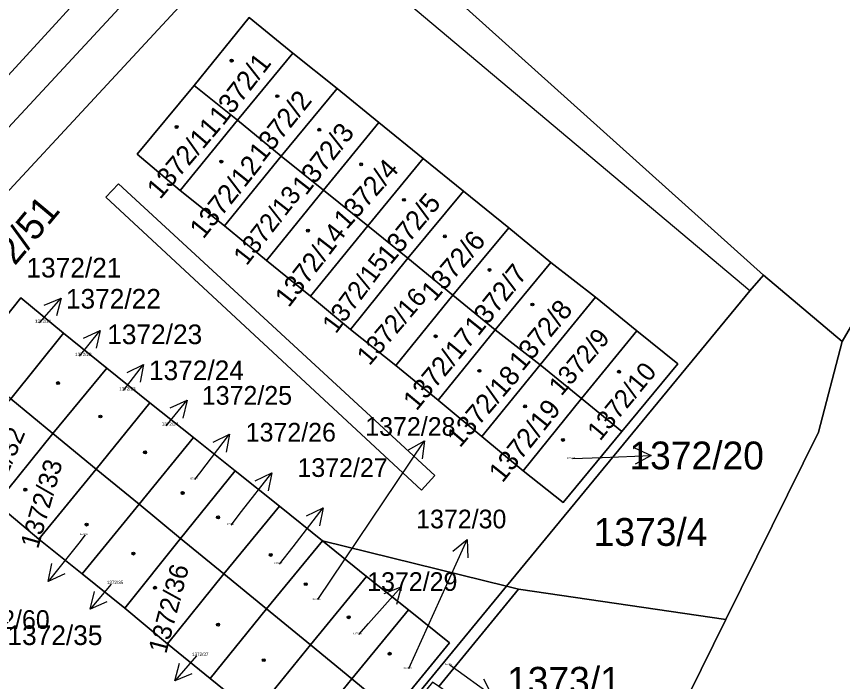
# Model space of a CAD drawing. Extents: x -598934 to -598196, y -1162208 to -1161502.
# Drawn here: x -598490.4 to -598440, y -1161798.5 to -1161757.9 of the extents above; entities that cross this region are included whole.
import ezdxf

# ---------------------------------------------------------------- set-up
doc = ezdxf.new("R2010")
doc.units = 0
for name, color, linetype in [('KN_CAR_KR', 7, 'Continuous'), ('KN_KULTURY', 7, 'Continuous'), ('KN_PARC_CIS_POM', 7, 'Continuous'), ('KN_PARC_CIS_POZ', 7, 'Continuous'), ('KN_PARC_CIS_STAV', 7, 'Continuous'), ('KN_PARC_PLOCHA', 7, 'Continuous'), ('PARC_C_SIPKA', 7, 'Continuous'), ('parcely_l', 7, 'Continuous')]:
    doc.layers.add(name, color=color, linetype=linetype)

msp = doc.modelspace()

# ---------------------------------------------------------------- linework, layer by layer
at = {"layer": 'KN_CAR_KR'}
for points in [[(-598477.15, -1161746.44), (-598498.32, -1161769.54)], [(-598474.27, -1161750.6), (-598503.05, -1161781.64)], [(-598445.66, -1161774.67), (-598474.27, -1161750.6)], [(-598484.99, -1161768.95), (-598484.21, -1161768.15)], [(-598484.21, -1161768.15), (-598464.88, -1161785.95)], [(-598465.7, -1161786.85), (-598484.99, -1161768.95)], [(-598464.88, -1161785.95), (-598465.7, -1161786.85)]]:
    msp.add_lwpolyline(points, dxfattribs=at)
at = {"layer": 'KN_KULTURY'}
for centre, radius in [((-598477.3, -1161760.62), 0.09), ((-598477.3, -1161760.62), 0.0398), ((-598474.51, -1161762.79), 0.09), ((-598474.51, -1161762.79), 0.0398), ((-598480.66, -1161764.67), 0.09), ((-598480.66, -1161764.67), 0.0398), ((-598471.95, -1161764.84), 0.09), ((-598471.95, -1161764.84), 0.0398), ((-598477.93, -1161766.78), 0.09), ((-598477.93, -1161766.78), 0.0398), ((-598469.39, -1161766.95), 0.09), ((-598469.39, -1161766.95), 0.0398), ((-598466.78, -1161769.12), 0.09), ((-598466.78, -1161769.12), 0.0398), ((-598472.64, -1161771), 0.09), ((-598472.64, -1161771), 0.0398), ((-598464.28, -1161771.35), 0.09), ((-598464.28, -1161771.35), 0.0398), ((-598461.55, -1161773.4), 0.09), ((-598461.55, -1161773.4), 0.0398), ((-598458.93, -1161775.51), 0.09), ((-598458.93, -1161775.51), 0.0398), ((-598464.84, -1161777.45), 0.09), ((-598464.84, -1161777.45), 0.0398), ((-598462.17, -1161779.56), 0.09), ((-598462.17, -1161779.56), 0.0398), ((-598453.64, -1161779.62), 0.09), ((-598453.64, -1161779.62), 0.0398), ((-598487.9, -1161780.31), 0.09), ((-598487.9, -1161780.31), 0.0398), ((-598459.38, -1161781.73), 0.09), ((-598459.38, -1161781.73), 0.0398), ((-598485.31, -1161782.35), 0.09), ((-598485.31, -1161782.35), 0.0398), ((-598457.07, -1161783.78), 0.09), ((-598457.07, -1161783.78), 0.0398), ((-598482.59, -1161784.54), 0.09), ((-598482.59, -1161784.54), 0.0398), ((-598489.9, -1161786.82), 0.09), ((-598489.9, -1161786.82), 0.0398), ((-598480.29, -1161787.02), 0.09), ((-598480.29, -1161787.02), 0.0398), ((-598478.13, -1161788.51), 0.09), ((-598478.13, -1161788.51), 0.0398), ((-598486.16, -1161788.95), 0.09), ((-598486.16, -1161788.95), 0.0398), ((-598483.3, -1161790.72), 0.09), ((-598483.3, -1161790.72), 0.0398), ((-598474.91, -1161790.8), 0.09), ((-598474.91, -1161790.8), 0.0398), ((-598481.98, -1161792.81), 0.09), ((-598481.98, -1161792.81), 0.0398), ((-598472.77, -1161792.59), 0.09), ((-598472.77, -1161792.59), 0.0398), ((-598470.15, -1161794.61), 0.09), ((-598470.15, -1161794.61), 0.0398), ((-598478.13, -1161795.06), 0.09), ((-598478.13, -1161795.06), 0.0398), ((-598467.65, -1161796.84), 0.09), ((-598467.65, -1161796.84), 0.0398), ((-598475.34, -1161797.23), 0.09), ((-598475.34, -1161797.23), 0.0398)]:
    msp.add_circle(centre, radius, dxfattribs=at)
at = {"layer": 'KN_PARC_PLOCHA'}
for points in [[(-598468.63, -1161720.8), (-598458.77, -1161729.49), (-598474.53, -1161747.01), (-598505.54, -1161780.43), (-598505.91, -1161780.84), (-598507.88, -1161780.28), (-598515.19, -1161778.23), (-598542.18, -1161767.07), (-598540.95, -1161765.46), (-598543.04, -1161763.56), (-598545.78, -1161761.07), (-598536.13, -1161750.75), (-598533.19, -1161747.65), (-598527.64, -1161741.82), (-598526.22, -1161740.28), (-598520.88, -1161734.41), (-598507.87, -1161720.56), (-598509.16, -1161719.36), (-598497.98, -1161707.55), (-598490.92, -1161710.74), (-598487.64, -1161712.22), (-598474.84, -1161718), (-598472.67, -1161718.98)], [(-598444.82, -1161773.72), (-598445.66, -1161774.67), (-598460.51, -1161792.71), (-598471.76, -1161789.95), (-598474.37, -1161787.83), (-598477.08, -1161785.67), (-598479.63, -1161783.63), (-598482.3, -1161781.51), (-598484.93, -1161779.4), (-598487.57, -1161777.27), (-598490.17, -1161775.1), (-598493.4, -1161779.13), (-598496.93, -1161783.36), (-598503.05, -1161781.64), (-598505.91, -1161780.84), (-598505.54, -1161780.43), (-598474.53, -1161747.01)], [(-598479.58, -1161762.13), (-598483.06, -1161766.34), (-598480.44, -1161768.55), (-598477.74, -1161770.7), (-598475.18, -1161772.83), (-598472.48, -1161775), (-598470.03, -1161777.03), (-598467.28, -1161779.24), (-598464.69, -1161781.36), (-598462.01, -1161783.58), (-598459.5, -1161785.67), (-598457.05, -1161787.61), (-598453.46, -1161783.27), (-598450.05, -1161779.13), (-598452.55, -1161777.12), (-598455.08, -1161775.07), (-598457.8, -1161772.94), (-598460.37, -1161770.83), (-598463.13, -1161768.58), (-598465.6, -1161766.6), (-598468.3, -1161764.39), (-598470.85, -1161762.33), (-598473.57, -1161760.17), (-598476.23, -1161757.98)], [(-598473.57, -1161760.17), (-598476.94, -1161764.26), (-598479.58, -1161762.13), (-598476.23, -1161757.98)], [(-598470.85, -1161762.33), (-598474.27, -1161766.45), (-598476.94, -1161764.26), (-598473.57, -1161760.17)], [(-598476.94, -1161764.26), (-598480.44, -1161768.55), (-598483.06, -1161766.34), (-598479.58, -1161762.13)], [(-598468.3, -1161764.39), (-598471.69, -1161768.53), (-598474.27, -1161766.45), (-598470.85, -1161762.33)], [(-598474.27, -1161766.45), (-598477.74, -1161770.7), (-598480.44, -1161768.55), (-598476.94, -1161764.26)], [(-598465.6, -1161766.6), (-598468.98, -1161770.71), (-598471.69, -1161768.53), (-598468.3, -1161764.39)], [(-598471.69, -1161768.53), (-598475.18, -1161772.83), (-598477.74, -1161770.7), (-598474.27, -1161766.45)], [(-598463.13, -1161768.58), (-598466.54, -1161772.68), (-598468.98, -1161770.71), (-598465.6, -1161766.6)], [(-598468.98, -1161770.71), (-598472.48, -1161775), (-598475.18, -1161772.83), (-598471.69, -1161768.53)], [(-598460.37, -1161770.83), (-598463.79, -1161774.95), (-598466.54, -1161772.68), (-598463.13, -1161768.58)], [(-598466.54, -1161772.68), (-598470.03, -1161777.03), (-598472.48, -1161775), (-598468.98, -1161770.71)], [(-598457.8, -1161772.94), (-598461.2, -1161777.06), (-598463.79, -1161774.95), (-598460.37, -1161770.83)], [(-598463.79, -1161774.95), (-598467.28, -1161779.24), (-598470.03, -1161777.03), (-598466.54, -1161772.68)], [(-598455.08, -1161775.07), (-598458.46, -1161779.2), (-598461.2, -1161777.06), (-598457.8, -1161772.94)], [(-598440.02, -1161777.77), (-598441.46, -1161783.3), (-598447.12, -1161794.75), (-598459.77, -1161792.89), (-598460.51, -1161792.71), (-598445.66, -1161774.67), (-598444.82, -1161773.72)], [(-598487.57, -1161777.27), (-598490.79, -1161781.27), (-598493.4, -1161779.13), (-598490.17, -1161775.1)], [(-598461.2, -1161777.06), (-598464.69, -1161781.36), (-598467.28, -1161779.24), (-598463.79, -1161774.95)], [(-598452.55, -1161777.12), (-598455.94, -1161781.26), (-598458.46, -1161779.2), (-598455.08, -1161775.07)], [(-598458.46, -1161779.2), (-598462.01, -1161783.58), (-598464.69, -1161781.36), (-598461.2, -1161777.06)], [(-598453.46, -1161783.27), (-598455.94, -1161781.26), (-598452.55, -1161777.12), (-598450.05, -1161779.13)], [(-598484.93, -1161779.4), (-598488.22, -1161783.38), (-598490.79, -1161781.27), (-598487.57, -1161777.27)], [(-598482.3, -1161781.51), (-598485.58, -1161785.56), (-598488.22, -1161783.38), (-598484.93, -1161779.4)], [(-598455.94, -1161781.26), (-598459.5, -1161785.67), (-598462.01, -1161783.58), (-598458.46, -1161779.2)], [(-598488.22, -1161783.38), (-598491.67, -1161787.66), (-598494.32, -1161785.51), (-598490.79, -1161781.27)], [(-598479.63, -1161783.63), (-598482.94, -1161787.7), (-598485.58, -1161785.56), (-598482.3, -1161781.51)], [(-598453.46, -1161783.27), (-598457.05, -1161787.61), (-598459.5, -1161785.67), (-598455.94, -1161781.26)], [(-598485.58, -1161785.56), (-598489.08, -1161789.85), (-598491.67, -1161787.66), (-598488.22, -1161783.38)], [(-598477.08, -1161785.67), (-598480.43, -1161789.8), (-598482.94, -1161787.7), (-598479.63, -1161783.63)], [(-598482.94, -1161787.7), (-598486.42, -1161791.96), (-598489.08, -1161789.85), (-598485.58, -1161785.56)], [(-598474.37, -1161787.83), (-598477.78, -1161791.96), (-598480.43, -1161789.8), (-598477.08, -1161785.67)], [(-598480.43, -1161789.8), (-598483.83, -1161794.06), (-598486.42, -1161791.96), (-598482.94, -1161787.7)], [(-598471.76, -1161789.95), (-598475.17, -1161794.09), (-598477.78, -1161791.96), (-598474.37, -1161787.83)], [(-598477.78, -1161791.96), (-598481.22, -1161796.24), (-598483.83, -1161794.06), (-598480.43, -1161789.8)], [(-598469.07, -1161792.12), (-598472.48, -1161796.3), (-598475.17, -1161794.09), (-598471.76, -1161789.95)], [(-598475.17, -1161794.09), (-598478.61, -1161798.34), (-598481.22, -1161796.24), (-598477.78, -1161791.96)], [(-598466.5, -1161794.15), (-598469.95, -1161798.37), (-598472.48, -1161796.3), (-598469.07, -1161792.12)], [(-598459.77, -1161792.89), (-598464.65, -1161798.84), (-598465.04, -1161798.57), (-598470.35, -1161805.13), (-598470, -1161805.38), (-598471.34, -1161807.01), (-598471.92, -1161806.57), (-598460.51, -1161792.71)], [(-598447.12, -1161794.75), (-598453.12, -1161806.91), (-598464.65, -1161798.84), (-598459.77, -1161792.89)], [(-598472.48, -1161796.3), (-598475.93, -1161800.53), (-598478.61, -1161798.34), (-598475.17, -1161794.09)], [(-598467.48, -1161800.42), (-598469.95, -1161798.37), (-598466.5, -1161794.15), (-598464, -1161796.18)], [(-598469.95, -1161798.37), (-598473.39, -1161802.6), (-598475.93, -1161800.53), (-598472.48, -1161796.3)], [(-598467.48, -1161800.42), (-598470.88, -1161804.64), (-598473.39, -1161802.6), (-598469.95, -1161798.37)]]:
    msp.add_lwpolyline(points, close=True, dxfattribs=at)
for points in [[(-598427.55, -1161756.32), (-598440.02, -1161777.77), (-598444.82, -1161773.72), (-598474.53, -1161747.01)], [(-598410.62, -1161891.48), (-598418.63, -1161877.72), (-598427.39, -1161865.4), (-598433.67, -1161869.8), (-598434.1, -1161869.15), (-598445.71, -1161871.58), (-598449.31, -1161869.76), (-598449.61, -1161869.08), (-598454.58, -1161857.52), (-598455.59, -1161855.48), (-598455.84, -1161854.98), (-598459.74, -1161846.72), (-598467, -1161832.7), (-598458.45, -1161816.73), (-598457.26, -1161814.63), (-598454.25, -1161816.82), (-598448.74, -1161809.99), (-598453.12, -1161806.91), (-598447.12, -1161794.75), (-598441.46, -1161783.3), (-598440.02, -1161777.77), (-598427.55, -1161756.32)], [(-598491.67, -1161787.66), (-598489.08, -1161789.85), (-598486.42, -1161791.96), (-598483.83, -1161794.06), (-598481.22, -1161796.24), (-598478.61, -1161798.34), (-598475.93, -1161800.53)], [(-598467.48, -1161800.42), (-598464, -1161796.18), (-598466.5, -1161794.15), (-598469.07, -1161792.12), (-598471.76, -1161789.95), (-598460.51, -1161792.71), (-598471.92, -1161806.57)]]:
    msp.add_lwpolyline(points, dxfattribs=at)
at = {"layer": 'PARC_C_SIPKA'}
for points in [[(-598489.04, -1161776.63), (-598487.703, -1161775.129)], [(-598488.742, -1161775.543), (-598487.703, -1161775.129), (-598487.995, -1161776.208)], [(-598486.59, -1161778.66), (-598485.332, -1161777.093)], [(-598486.348, -1161777.559), (-598485.332, -1161777.093), (-598485.568, -1161778.185)], [(-598483.9, -1161780.76), (-598482.677, -1161779.165)], [(-598483.682, -1161779.654), (-598482.677, -1161779.165), (-598482.889, -1161780.262)], [(-598481.3, -1161782.91), (-598480.025, -1161781.356)], [(-598481.046, -1161781.812), (-598480.025, -1161781.356), (-598480.273, -1161782.446)], [(-598479.54, -1161786.19), (-598479.25, -1161785.81), (-598477.43, -1161783.425)], [(-598478.434, -1161783.917), (-598477.43, -1161783.425), (-598477.639, -1161784.523)], [(-598472.03, -1161793.53), (-598467.19, -1161786.32), (-598465.519, -1161783.828)], [(-598466.492, -1161784.38), (-598465.519, -1161783.828), (-598465.661, -1161784.937)], [(-598452.702, -1161784.269), (-598451.683, -1161784.727), (-598452.661, -1161785.268)], [(-598456.49, -1161784.92), (-598454.68, -1161784.85), (-598451.683, -1161784.727)], [(-598477.33, -1161788.98), (-598476.69, -1161788.16), (-598474.845, -1161785.794)], [(-598475.854, -1161786.275), (-598474.845, -1161785.794), (-598475.066, -1161786.89)], [(-598474.37, -1161791.36), (-598473.55, -1161790.3), (-598471.712, -1161787.929)], [(-598472.72, -1161788.413), (-598471.712, -1161787.929), (-598471.929, -1161789.026)], [(-598486.24, -1161789.58), (-598486.64, -1161790.08), (-598488.51, -1161792.426)], [(-598466.47, -1161797.74), (-598464.15, -1161792.6), (-598462.917, -1161789.865)], [(-598463.784, -1161790.571), (-598462.917, -1161789.865), (-598462.872, -1161790.982)], [(-598487.495, -1161791.956), (-598488.51, -1161792.426), (-598488.277, -1161791.333)], [(-598484.65, -1161792.58), (-598485.94, -1161794.122)], [(-598469.54, -1161795.66), (-598468.94, -1161794.99), (-598466.937, -1161792.757)], [(-598467.977, -1161793.168), (-598466.937, -1161792.757), (-598467.232, -1161793.835)], [(-598484.915, -1161793.676), (-598485.94, -1161794.122), (-598485.682, -1161793.034)], [(-598479.45, -1161796.97), (-598480.762, -1161798.493)], [(-598479.73, -1161798.062), (-598480.762, -1161798.493), (-598480.488, -1161797.409)], [(-598463.98, -1161797.52), (-598463.84, -1161797.62), (-598461.402, -1161799.368)], [(-598461.923, -1161798.379), (-598461.402, -1161799.368), (-598462.506, -1161799.192)]]:
    msp.add_lwpolyline(points, dxfattribs=at)
at = {"layer": 'parcely_l'}
for points in [[(-598440.02, -1161777.77), (-598427.55, -1161756.32), (-598426.83, -1161755.55), (-598413, -1161741.14), (-598401.62, -1161728.95), (-598389.25, -1161722.01), (-598384.3, -1161719.62)], [(-598505.91, -1161780.84), (-598505.54, -1161780.43), (-598474.53, -1161747.01)], [(-598474.53, -1161747.01), (-598444.82, -1161773.72)], [(-598473.57, -1161760.17), (-598476.23, -1161757.98), (-598479.58, -1161762.13)], [(-598476.94, -1161764.26), (-598473.57, -1161760.17)], [(-598470.85, -1161762.33), (-598473.57, -1161760.17)], [(-598479.58, -1161762.13), (-598483.06, -1161766.34), (-598480.44, -1161768.55)], [(-598479.58, -1161762.13), (-598476.94, -1161764.26)], [(-598470.85, -1161762.33), (-598474.27, -1161766.45)], [(-598468.3, -1161764.39), (-598470.85, -1161762.33)], [(-598476.94, -1161764.26), (-598480.44, -1161768.55)], [(-598474.27, -1161766.45), (-598476.94, -1161764.26)], [(-598471.69, -1161768.53), (-598468.3, -1161764.39)], [(-598465.6, -1161766.6), (-598468.3, -1161764.39)], [(-598474.27, -1161766.45), (-598477.74, -1161770.7)], [(-598474.27, -1161766.45), (-598471.69, -1161768.53)], [(-598468.98, -1161770.71), (-598465.6, -1161766.6)], [(-598463.13, -1161768.58), (-598465.6, -1161766.6)], [(-598480.44, -1161768.55), (-598477.74, -1161770.7)], [(-598475.18, -1161772.83), (-598471.69, -1161768.53)], [(-598471.69, -1161768.53), (-598468.98, -1161770.71)], [(-598463.13, -1161768.58), (-598466.54, -1161772.68)], [(-598460.37, -1161770.83), (-598463.13, -1161768.58)], [(-598477.74, -1161770.7), (-598475.18, -1161772.83)], [(-598468.98, -1161770.71), (-598472.48, -1161775)], [(-598466.54, -1161772.68), (-598468.98, -1161770.71)], [(-598463.79, -1161774.95), (-598460.37, -1161770.83)], [(-598457.8, -1161772.94), (-598460.37, -1161770.83)], [(-598472.48, -1161775), (-598475.18, -1161772.83)], [(-598466.54, -1161772.68), (-598470.03, -1161777.03)], [(-598463.79, -1161774.95), (-598466.54, -1161772.68)], [(-598461.2, -1161777.06), (-598457.8, -1161772.94)], [(-598455.08, -1161775.07), (-598457.8, -1161772.94)], [(-598444.82, -1161773.72), (-598445.66, -1161774.67), (-598460.51, -1161792.71)], [(-598444.82, -1161773.72), (-598440.02, -1161777.77)], [(-598487.57, -1161777.27), (-598490.17, -1161775.1), (-598493.4, -1161779.13)], [(-598472.48, -1161775), (-598470.03, -1161777.03)], [(-598467.28, -1161779.24), (-598463.79, -1161774.95)], [(-598461.2, -1161777.06), (-598463.79, -1161774.95)], [(-598458.46, -1161779.2), (-598455.08, -1161775.07)], [(-598452.55, -1161777.12), (-598455.08, -1161775.07)], [(-598470.03, -1161777.03), (-598467.28, -1161779.24)], [(-598464.69, -1161781.36), (-598461.2, -1161777.06)], [(-598458.46, -1161779.2), (-598461.2, -1161777.06)], [(-598452.55, -1161777.12), (-598455.94, -1161781.26)], [(-598453.46, -1161783.27), (-598450.05, -1161779.13), (-598452.55, -1161777.12)], [(-598487.57, -1161777.27), (-598490.79, -1161781.27)], [(-598484.93, -1161779.4), (-598487.57, -1161777.27)], [(-598447.12, -1161794.75), (-598441.46, -1161783.3), (-598440.02, -1161777.77)], [(-598488.22, -1161783.38), (-598484.93, -1161779.4)], [(-598482.3, -1161781.51), (-598484.93, -1161779.4)], [(-598467.28, -1161779.24), (-598464.69, -1161781.36)], [(-598458.46, -1161779.2), (-598462.01, -1161783.58)], [(-598455.94, -1161781.26), (-598458.46, -1161779.2)], [(-598490.79, -1161781.27), (-598488.22, -1161783.38)], [(-598485.58, -1161785.56), (-598482.3, -1161781.51)], [(-598479.63, -1161783.63), (-598482.3, -1161781.51)], [(-598464.69, -1161781.36), (-598462.01, -1161783.58)], [(-598459.5, -1161785.67), (-598455.94, -1161781.26)], [(-598455.94, -1161781.26), (-598453.46, -1161783.27)], [(-598491.67, -1161787.66), (-598488.22, -1161783.38)], [(-598488.22, -1161783.38), (-598485.58, -1161785.56)], [(-598479.63, -1161783.63), (-598482.94, -1161787.7)], [(-598477.08, -1161785.67), (-598479.63, -1161783.63)], [(-598462.01, -1161783.58), (-598459.5, -1161785.67)], [(-598459.5, -1161785.67), (-598457.05, -1161787.61), (-598453.46, -1161783.27)], [(-598485.58, -1161785.56), (-598489.08, -1161789.85)], [(-598485.58, -1161785.56), (-598482.94, -1161787.7)], [(-598480.43, -1161789.8), (-598477.08, -1161785.67)], [(-598474.37, -1161787.83), (-598477.08, -1161785.67)], [(-598489.08, -1161789.85), (-598491.67, -1161787.66)], [(-598482.94, -1161787.7), (-598486.42, -1161791.96)], [(-598482.94, -1161787.7), (-598480.43, -1161789.8)], [(-598477.78, -1161791.96), (-598474.37, -1161787.83)], [(-598474.37, -1161787.83), (-598471.76, -1161789.95)], [(-598486.42, -1161791.96), (-598489.08, -1161789.85)], [(-598483.83, -1161794.06), (-598480.43, -1161789.8)], [(-598477.78, -1161791.96), (-598480.43, -1161789.8)], [(-598471.76, -1161789.95), (-598475.17, -1161794.09)], [(-598460.51, -1161792.71), (-598471.76, -1161789.95)], [(-598471.76, -1161789.95), (-598469.07, -1161792.12)], [(-598486.42, -1161791.96), (-598483.83, -1161794.06)], [(-598477.78, -1161791.96), (-598481.22, -1161796.24)], [(-598475.17, -1161794.09), (-598477.78, -1161791.96)], [(-598469.07, -1161792.12), (-598472.48, -1161796.3)], [(-598466.5, -1161794.15), (-598469.07, -1161792.12)], [(-598471.92, -1161806.57), (-598460.51, -1161792.71)], [(-598460.51, -1161792.71), (-598459.77, -1161792.89)], [(-598464.65, -1161798.84), (-598459.77, -1161792.89)], [(-598459.77, -1161792.89), (-598447.12, -1161794.75)], [(-598481.22, -1161796.24), (-598483.83, -1161794.06)], [(-598478.61, -1161798.34), (-598475.17, -1161794.09)], [(-598472.48, -1161796.3), (-598475.17, -1161794.09)], [(-598469.95, -1161798.37), (-598466.5, -1161794.15)], [(-598466.5, -1161794.15), (-598464, -1161796.18), (-598467.48, -1161800.42)], [(-598453.12, -1161806.91), (-598447.12, -1161794.75)], [(-598478.61, -1161798.34), (-598481.22, -1161796.24)], [(-598475.93, -1161800.53), (-598472.48, -1161796.3)], [(-598472.48, -1161796.3), (-598469.95, -1161798.37)], [(-598475.93, -1161800.53), (-598478.61, -1161798.34)], [(-598469.95, -1161798.37), (-598473.39, -1161802.6)], [(-598467.48, -1161800.42), (-598469.95, -1161798.37)]]:
    msp.add_lwpolyline(points, dxfattribs=at)

# ---------------------------------------------------------------- texts
at = {"layer": 'KN_PARC_CIS_POM'}
for s, height, p in [('1372/21', 0.2, (-598489.307, -1161776.63)), ('1372/22', 0.2, (-598486.857, -1161778.66)), ('1372/23', 0.2, (-598484.167, -1161780.76)), ('1372/24', 0.2, (-598481.567, -1161782.91)), ('1372/20', 0.1, (-598456.823, -1161784.92)), ('1372/25', 0.1, (-598479.873, -1161786.19)), ('1372/26', 0.1, (-598477.663, -1161788.98)), ('1372/60', 0.1, (-598486.573, -1161789.58)), ('1372/27', 0.1, (-598474.703, -1161791.36)), ('1372/35', 0.2, (-598484.917, -1161792.58)), ('1372/28', 0.1, (-598472.363, -1161793.53)), ('1372/29', 0.1, (-598469.873, -1161795.66)), ('1372/37', 0.2, (-598479.717, -1161796.97)), ('1372/30', 0.1, (-598466.803, -1161797.74)), ('1373/5', 0.1, (-598464.263, -1161797.52))]:
    msp.add_text(s, height=height, dxfattribs=at).set_placement(p)
at = {"layer": 'KN_PARC_CIS_POZ'}
for s, height, rotation, p in [('1372/13', 1.14, 52.0772, (-598476.385, -1161773.188)), ('1372/51', 1.7, 50.0719, (-598492.978, -1161776.094)), ('1372/15', 1.14, 53.3662, (-598470.937, -1161777.349)), ('1372/16', 1.14, 49.4601, (-598468.89, -1161779.298)), ('1372/9', 1.14, 49.5539, (-598457.165, -1161781.148)), ('1372/32', 1.14, 66.9756, (-598492.036, -1161788.397))]:
    msp.add_text(s, height=height, rotation=rotation, dxfattribs=at).set_placement(p)
at = {"layer": 'KN_PARC_CIS_STAV'}
for s, height, rotation, p in [('1372/1', 1.2, 52.2005, (-598477.827, -1161764.647)), ('1372/2', 1.2, 51.3001, (-598475.403, -1161766.895)), ('1372/11', 1.2, 49.4992, (-598481.669, -1161769.137)), ('1372/3', 1.2, 52.2005, (-598472.757, -1161768.907)), ('1372/12', 1.2, 51.2999, (-598479.03, -1161771.559)), ('1372/4', 1.2, 48.6004, (-598470.27, -1161770.985)), ('1372/5', 1.2, 50.4002, (-598467.589, -1161773.132)), ('1372/14', 1.2, 52.1992, (-598473.811, -1161775.744)), ('1372/6', 1.2, 49.4998, (-598464.914, -1161775.388)), ('1372/7', 1.2, 51.3001, (-598462.243, -1161777.495)), ('1372/8', 1.2, 50.4002, (-598459.539, -1161779.642)), ('1372/17', 1.2, 50.4006, (-598466.01, -1161782.053)), ('1372/10', 1.14, 50.3992, (-598454.799, -1161783.891)), ('1372/18', 1.2, 49.4992, (-598463.359, -1161784.307)), ('1372/19', 1.2, 51.2999, (-598460.76, -1161786.449)), ('1372/33', 1.14, 74.0539, (-598489.124, -1161790.474)), ('1372/36', 1.14, 75.2318, (-598481.299, -1161796.884))]:
    msp.add_text(s, height=height, rotation=rotation, dxfattribs=at).set_placement(p)
for s, height, p in [('1372/21', 1.2, (-598489.831, -1161773.862)), ('1372/22', 1.2, (-598487.421, -1161775.762)), ('1372/23', 1.2, (-598484.897, -1161777.931)), ('1372/24', 1.2, (-598482.349, -1161780.131)), ('1372/25', 1.14, (-598479.12, -1161781.63)), ('1372/26', 1.14, (-598476.44, -1161783.88)), ('1372/28', 1.14, (-598469.14, -1161783.53)), ('1372/20', 1.7, (-598453.007, -1161785.58)), ('1372/27', 1.14, (-598473.28, -1161786.04)), ('1372/30', 1.14, (-598466.03, -1161789.18)), ('1373/4', 1.7, (-598455.192, -1161790.25)), ('1372/29', 1.14, (-598469.02, -1161793)), ('1372/60', 1.14, (-598493.92, -1161795.32)), ('1372/35', 1.2, (-598490.991, -1161796.306)), ('1373/1', 1.7, (-598460.482, -1161799.34))]:
    msp.add_text(s, height=height, dxfattribs=at).set_placement(p)

doc.saveas('drawing.dxf')
